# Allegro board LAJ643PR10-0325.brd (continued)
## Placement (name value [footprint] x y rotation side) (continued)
CK9  100P_0201_50V8J  [C_0201]  137.25 25.59 90 top
CK10  1000P_0402_50V8K  [C_0402]  148.19 6.57 270 top
CK11  0.1U_0402_16V7K  [C_0402]  128.42 22.22 270 top
CK12  1000P_0402_50V8K  [C_0402]  129.34 23.16 270 top
CK13  0.1U_0402_16V7K  [C_0402]  133.08 16.18 180 top
CK14  0.1U_0402_16V7K  [C_0402]  190.51 21.07 90 top
CK15  100P_0402_50V8J  [C_0402]  147.17 25.51 90 top
CK16  0.1U_0201_10V6K  [C_0201]  132.26 13.46 180 top
CL1  0.01U_0402_16V7K  [C_0402]  46.74 32.54 0 top
CL2  10P_1808_3KV  [C_1808]  41.76 43.3 270 bottom
CL3  120P_0402_50V8J  [C_0402]  34.75 43.69 270 bottom
CL4  0.1U_0402_16V7K  [C_0402]  47.66 26.44 180 top
CL5  0.1U_0201_10V6K  [C_0201]  52.15 22.97 90 bottom
CL8  4.7U_0402_6.3V6M  [C_0402]  51.51 13.39 270 bottom
CL9  0.1U_0201_10V6K  [C_0201]  59.52 20.56 90 bottom
CL10  4.7U_0402_6.3V6M  [C_0402]  54.31 15.59 270 bottom
CL11  0.1U_0201_10V6K  [C_0201]  52.15 21.45 90 bottom
CL12  0.1U_0201_10V6K  [C_0201]  59.01 23.01 0 bottom
CL13  0.1U_0201_10V6K  [C_0201]  55.16 16.03 0 bottom
CL14  0.1U_0201_10V6K  [C_0201]  55.16 14.76 0 bottom
CL15  1U_0201_6.3V6M  [C_0201]  55.16 15.39 0 bottom
CL16  0.1U_0201_10V6K  [C_0201]  54.48 16.41 180 bottom
CL19  4.7U_0402_6.3V6M  [C_0402]  51.37 23.22 180 bottom
CL20  4.7U_0402_6.3V6M  [C_0402]  60.3 20.77 90 bottom
CL23  0.1U_0201_10V6K  [C_0201]  52.27 13.23 270 bottom
CL24  10P_0402_50V8J  [C_0402]  50.88 20.34 270 bottom
CL25  10P_0402_50V8J  [C_0402]  50.88 17.68 90 bottom
CL26  0.1U_0201_10V6K  [C_0201]  55.07 23.35 90 bottom
CL27  1U_0201_6.3V6M  [C_0201]  51.05 21.49 180 bottom
CL28  1500P_0402_50V7K  [C_0402]  61.12 13.84 0 bottom
CL29  4.7U_0402_6.3V6M  [C_0402]  52.55 16.11 180 top
CLRP1  SHORT PADS  [SHORTPADS]  188.8 17.68 90 top
CLRP2  SHORT PADS  [SHORTPADS]  188.55 20.85 0 top
CLRP3  SHORT PADS  [SHORTPADS]  215.63 20.37 180 top
CR1  0.1U_0402_16V7K  [C_0402]  37.17 21.61 0 top
CR2  0.1U_0402_16V7K  [C_0402]  37.8 16.41 180 bottom
CR3  4.7U_0402_6.3V6M  [C_0402]  45.42 18.82 0 bottom
CR4  10U_0402_6.3V6M  [C_0402]  37.17 20.72 0 top
CR6  0.1U_0402_16V7K  [C_0402]  45.42 17.93 0 bottom
CR7  10U_0402_6.3V6M  [C_0402]  37.8 15.52 180 bottom
CR9  4.7U_0402_6.3V6M  [C_0402]  37.8 18.18 180 bottom
CR10  0.1U_0402_16V7K  [C_0402]  37.8 17.3 180 bottom
CR11  0.1U_0402_10V7K  [C_0402]  60.32 16.84 180 bottom
CR12  6.8P_0402_50V8C  [C_0402]  38.56 21.61 270 bottom
CR13  0.1U_0402_10V7K  [C_0402]  60.32 15.95 180 bottom
CR14  0.1U_0402_10V7K  [C_0402]  39.62 12.15 90 bottom
CR15  0.1U_0402_10V7K  [C_0402]  38.73 12.15 90 bottom
CR16  0.1U_0402_16V7K  [C_0402]  39.65 15.79 90 top
CR17  1U_0201_6.3V6M  [C_0201]  40.21 20.72 90 bottom
CS7  0.1U_0402_16V7K  [C_0402]  20.66 76.99 270 bottom
CS8  1U_0201_6.3V6M  [C_0201]  22.34 84.9 0 bottom
CS9  47U_0805_6.3V6M  [C_0805]  21.15 83.76 0 bottom
CS21  .1U_0402_16V7K  [C_0402]  20.74 82.69 90 top
CS22  10U_0603_6.3V6M  [C_0603]  21.69 76.29 270 top
CS29  0.1U_0402_16V7K  [C_0402]  21.03 90.32 0 bottom
CS34  0.1U_0402_16V7K  [C_0402]  21.03 89.43 0 bottom
CS107  0.1U_0402_16V7K  [C_0402]  23.63 76.37 270 top
CS108  0.1U_0402_25V7K  [C_0402]  18.08 82.33 180 top
CS109  1U_0201_6.3V6M  [C_0201]  20.5 85.88 180 bottom
CS110  10U_0402_6.3V6M  [C_0402]  22.74 76.37 270 top
CS111  10U_0402_6.3V6M  [C_0402]  20.46 76.37 270 top
CS113  10U_0402_6.3V6M  [C_0402]  21.63 82.69 90 top
CS114  22U_0603_6.3V6M  [C_0603]  22.69 82.8 90 top
CT3  0.1U_0201_10V6K  [C_0201]  36.15 48.16 180 top
CT5  0.1U_0201_10V6K  [C_0201]  36.45 49.55 180 top
CT17  0.1U_0201_10V6K  [C_0201]  36.15 48.79 180 top
CT19  0.1U_0201_10V6K  [C_0201]  36.45 50.19 180 top
CT20  0.1U_0201_10V6K  [C_0201]  36.33 50.95 180 top
CT21  0.1U_0201_10V6K  [C_0201]  36.33 51.59 180 top
CT22  0.1U_0201_10V6K  [C_0201]  36.33 52.35 180 top
CT24  0.1U_0201_10V6K  [C_0201]  36.33 52.98 180 top
CT270  10U_0402_6.3V6M  [C_0402]  38.5 54.46 270 top
CT271  0.1U_0201_6.3V6K  [C_0201]  27.72 54.76 180 top
CT272  0.1U_0201_6.3V6K  [C_0201]  29.21 48.4 90 bottom
CT273  0.1U_0201_6.3V6K  [C_0201]  29.86 48.4 90 bottom
CT274  0.1U_0201_6.3V6K  [C_0201]  35.53 54.19 270 top
CT279  0.22U_0201_25V6K  [C_0201]  26.73 51.78 0 top
CT280  0.22U_0201_25V6K  [C_0201]  26.73 51.14 0 top
CT281  0.22U_0201_25V6K  [C_0201]  26.73 49.92 0 top
CT282  0.22U_0201_25V6K  [C_0201]  26.73 50.56 0 top
CT283  0.1U_0201_10V6K  [C_0201]  31.72 57.29 90 top
CT284  0.1U_0201_10V6K  [C_0201]  30.83 57.29 90 top
CT285  0.1U_0201_10V6K  [C_0201]  31.91 45.73 270 top
CT286  0.1U_0201_10V6K  [C_0201]  31.32 45.73 270 top
CT287  0.1U_0201_10V6K  [C_0201]  33.89 45.88 270 top
CT288  0.1U_0201_10V6K  [C_0201]  33.29 45.88 270 top
CT319  0.33U_0201_25V6K  [C_0201]  26.27 52.99 0 top
CT320  0.33U_0201_25V6K  [C_0201]  26.27 52.36 0 top
CT321  0.33U_0201_25V6K  [C_0201]  27.06 48.11 0 top
CT322  0.33U_0201_25V6K  [C_0201]  27.06 48.74 0 top
CTT1  0.1U_0402_16V4Z  [C_0402]  119.03 13.99 180 top
CTT2  1U_0201_6.3V6M  [C_0201]  127.8 18.18 0 top
CTT3  0.1U_0402_16V4Z  [C_0402]  119.04 18.19 180 top
CTT4  0.1U_0402_16V4Z  [C_0402]  119.04 19.08 180 top
CTT323  1U_0201_6.3V6M  [C_0201]  123.99 12.98 0 top
CU57  0.47U_0402_25V6K  [C_0402]  11.62 52.71 90 top
CU58  0.47U_0402_25V6K  [C_0402]  10.73 52.71 90 top
CU59  0.47U_0402_25V6K  [C_0402]  11.19 50.95 90 top
CU60  0.47U_0402_25V6K  [C_0402]  12.08 51.84 270 top
CU61  22U_0603_6.3V6K  [C_0603]  39.92 42.83 270 top
CU62  4.7U_0402_6.3V6M  [C_0402]  41.91 41.67 90 top
CU63  1000P_0402_50V7K  [C_0402]  41.11 38.94 270 top
CU64  0.1U_0402_25V6  [C_0402]  42 38.94 270 top
CU65  1U_0603_25V6  [C_0603]  39.97 39.37 270 top
CU66  120P_0402_50V  [C_0402]  50.62 38.15 270 top
CU67  120P_0402_50V  [C_0402]  48.62 37.5 270 top
CU68  22P 50V J NPO 0402  [C_0402]  54.88 46.75 270 top
CU69  4.7U_0402_6.3V6M  [C_0402]  52.75 43.56 0 top
CU70  10U_0402_6.3V6M  [C_0402]  42 46.11 180 top
CU71  10U_0402_6.3V6M  [C_0402]  39.37 47.78 0 top
CU72  0.1U_0402_16V4Z  [C_0402]  60.92 23.31 0 bottom
CU73  4.7U_0402_6.3V6M  [C_0402]  49.7 38.15 270 top
CU74  4.7U_0402_6.3V6M  [C_0402]  55.4 44.5 270 top
CV1  22U_0603_6.3V6M  [C_0603]  73.8 37.11 0 top
CV2  68P_0402_50V8J  [C_0402]  78.01 38.76 180 top
CV3  22U_0603_6.3V6M  [C_0603]  68.48 33.89 180 top
CV4  22U_0603_6.3V6M  [C_0603]  69.66 32.74 0 top
CV5  680P_0402_50V7K  [C_0402]  79.41 30.76 180 top
CV6  68P_0402_50V8J  [C_0402]  79.41 29.87 180 top
CV7  .1U_0402_16V7K  [C_0402]  73.5 27.25 90 bottom
CV8  .1U_0402_16V7K  [C_0402]  72.61 27.25 90 bottom
CV9  .1U_0402_16V7K  [C_0402]  75.32 27.25 90 bottom
CV10  .1U_0402_16V7K  [C_0402]  74.43 27.25 90 bottom
CV11  .1U_0402_16V7K  [C_0402]  77.13 27.25 90 bottom
CV12  .1U_0402_16V7K  [C_0402]  76.24 27.25 90 bottom
CV13  .1U_0402_16V7K  [C_0402]  78.95 27.25 90 bottom
CV14  .1U_0402_16V7K  [C_0402]  78.06 27.25 90 bottom
CV15  .1U_0402_16V7K  [C_0402]  80.85 27.25 90 bottom
CV16  .1U_0402_16V7K  [C_0402]  79.96 27.25 90 bottom
CV17  220P_0402_50V7K  [C_0402]  71.63 24.32 270 bottom
CV18  220P_0402_50V7K  [C_0402]  71.79 26.27 270 bottom
CV19  4.7U_0402_6.3V6M  [C_0402]  28.77 59.03 0 top
CV20  0.1U_0402_10V6K  [C_0402]  25.84 58.82 90 top
CV21  0.1U_0402_10V6K  [C_0402]  27.21 58.84 90 top
CV22  0.01U_0402_16V7K  [C_0402]  24.49 58.8 90 top
CV23  0.1U_0402_10V6K  [C_0402]  23.22 58.24 90 top
CV24  0.1U_0402_10V6K  [C_0402]  22.73 62.62 0 top
CV25  0.01U_0402_16V7K  [C_0402]  25.87 64.01 270 top
CV26  0.1U_0402_10V6K  [C_0402]  28.99 59.96 180 top
CV27  0.1U_0402_10V6K  [C_0402]  22.76 61.28 0 top
CV28  0.01U_0402_16V7K  [C_0402]  24.51 63.99 270 top
CV29  0.1U_0402_10V6K  [C_0402]  27.21 64 270 top
CV30  0.01U_0402_16V7K  [C_0402]  28.76 61.28 180 top
CV31  0.1U_0402_10V6K  [C_0402]  28.07 66.19 90 top
CV32  0.01U_0402_16V7K  [C_0402]  28.15 66.29 90 bottom
CV33  0.1U_0402_10V6K  [C_0402]  20.66 57.33 270 top
CV34  0.1U_0402_10V6K  [C_0402]  31.33 57.34 180 bottom
CV35  0.1U_0402_10V6K  [C_0402]  31.33 56.38 180 bottom
CV36  0.1U_0402_10V6K  [C_0402]  26.88 55.5 90 bottom
CV37  0.1U_0402_10V6K  [C_0402]  25.99 55.5 90 bottom
CV38  0.1U_0402_10V6K  [C_0402]  24.97 55.5 90 bottom
CV39  0.1U_0402_10V6K  [C_0402]  24.08 55.5 90 bottom
CV40  0.1U_0402_10V6K  [C_0402]  23.07 55.5 90 bottom
CV41  0.1U_0402_10V6K  [C_0402]  22.18 55.5 90 bottom
CV43  1U_0201_6.3V6M  [C_0201]  28.28 56.24 90 top
CV44  1U_0201_6.3V6M  [C_0201]  21.39 56.28 90 top
CV45  .1U_0402_16V7K  [C_0402]  15.08 117.23 90 top
CV46  10P_0402_50V8J  [C_0402]  68.15 32.66 180 top
CV47  33P_0402_50V8J  [C_0402]  69.84 31.69 0 top
CV49  680P_0402_50V7K  [C_0402]  69.6 39.52 0 top
CV52  1000P_0402_50V7K  [C_0402]  15.97 118.12 270 top
CV53  1U_0201_6.3V6M  [C_0201]  27.65 56.24 90 top
CV54  10U_0402_6.3V6M  [C_0402]  87.54 33.46 0 top
CV273  2200P_0402_50V7K  [C_0402]  180.37 121.44 180 bottom
CV274  0.1U_0402_16V4K  [C_0402]  181.31 121.51 270 bottom
CV275  3.3P_0201_25V8B  [C_0201]  20.68 109.92 90 bottom
CW1  10U_0402_6.3V6M  [C_0402]  304.91 7.05 270 top
CWL1  100P_0402_50V8J  [C_0402]  310.09 21.82 0 top
CWL2  10U_0402_6.3V6M  [C_0402]  310.1 23.59 0 top
CWL3  10U_0402_6.3V6M  [C_0402]  307.4 7.96 180 top
CWL4  0.1U_0402_10V6K  [C_0402]  310.08 24.48 0 top
CWL5  0.1U_0402_10V6K  [C_0402]  307.4 7.01 180 top
CWL7  0.01U_0402_16V7K  [C_0402]  310.09 22.71 0 top
CWL8  0.01U_0402_16V7K  [C_0402]  310.65 6.5 0 top
D1  AZ5123-02S.R7G_SOT23-3  [AZ5123-02SPR7G_SOT23-3]  10.42 122.73 90 top
D3  AZ5123-02S.R7G_SOT23-3  [AZ5123-02SPR7G_SOT23-3]  207.98 128.93 0 top
D506  -  [AZC199-02SPR7G_SOT23-3]  65.31 28.08 0 bottom
D507  -  [AZC199-02SPR7G_SOT23-3]  69.27 25.07 180 bottom
D508  LRB751V-40T1G SOD-323  [CH751H-40PT_SOD323-2]  205.95 135.28 270 top
D510  RB751V-40 SOD-323  [CH751H-40PT_SOD323-2]  128.44 9.29 0 top
D511  LRB751V-40T1G_SOD323-2  [CH751H-40PT_SOD323-2]  182.38 48.74 270 top
D513  LRB751V-40T1G_SOD323-2  [CH751H-40PT_SOD323-2]  38.82 2.56 90 bottom
D514  RB751V-40 SOD-323  [CH751H-40PT_SOD323-2]  128.44 7.64 0 top
D516  LRB751V-40T1G_SOD323-2  [CH751H-40PT_SOD323-2]  176.03 45.97 90 top
D517  RB751V-40 SOD-323  [CH751H-40PT_SOD323-2]  111.71 25.17 270 top
DA1  AZ5125-01H.R7G_SOD523-2  [AZ5125-01HPR7G_SOD523-2]  289.01 25.93 180 top
DA3  -  [LRB521S-40T1G_SOD523-2-2]  292.82 12.85 90 top
DA8  -  [L03ESDL5V0CC3-2_SOT23-3]  295.76 37.86 270 top
DA9  -  [L03ESDL5V0CC3-2_SOT23-3]  295.76 41.96 270 top
DG1  -  [RB751S40T1G_SOD523-2]  245.95 39.77 0 bottom
DG2  -  [RB751S40T1G_SOD523-2]  220.49 64.84 90 top
DG3  -  [BAV70W_SOT323-3]  236.53 50.72 45 top
DG4  -  [RB751S40T1G_SOD523-2]  235.29 41.68 0 bottom
DG5  -  [RB751S40T1G_SOD523-2]  238.21 41.55 90 bottom
DG7  -  [RB751S40T1G_SOD523-2]  235.28 42.87 0 bottom
DG243  -  [RB751S40T1G_SOD523-2]  224.15 63.95 90 top
DH1  LBAT54CLT1G_SOT23-3  [BAT54C-7-F_SOT23-3]  179.99 12.52 90 top
DH2  LRB751V-40T1G_SOD323-2  [CH751H-40PT_SOD323-2]  191.22 16.28 0 top
DH3  LRB751V-40T1G_SOD323-2  [CH751H-40PT_SOD323-2]  188.68 14.63 0 top
DH4  LRB751V-40T1G_SOD323-2  [CH751H-40PT_SOD323-2]  204.67 6.32 0 top
DK2  LRB751V-40T1G_SOD323-2  [CH751H-40PT_SOD323-2]  131.57 20.97 90 top
DL1  -  [AZC199-02SPR7G_SOT23-3]  38.13 39.04 180 bottom
DM5  AZC099-04S.R7G_SOT23-6  [AZC099-04SPR7G_SOT23-6]  85.51 11.44 270 top
DM12  AZC099-04S.R7G_SOT-23-6-6  [YSUSB2P0-5_SOT-23-6-6]  52.56 27.76 270 bottom
DM13  AZC099-04S.R7G_SOT-23-6-6  [YSUSB2P0-5_SOT-23-6-6]  52.56 34.11 270 bottom
DM16  -  [AZC199-02SPR7G_SOT23-3]  8.13 59.97 270 top
DS5  -  [AZC199-02SPR7G_SOT23-3]  20.52 88.8 90 top
DS6  -  [AZ1045-04F_DFN2510P10E-10-9]  17.73 88.03 90 bottom
DT1  -  [AZC199-02SPR7G_SOT23-3]  95.2 14.53 180 top
DT2  LRB751V-40T1G_SOD323-2  [CH751H-40PT_SOD323-2]  20.87 51.97 180 bottom
DU1  -  [PUSB3FR4_DFN2510A-10-10]  14.08 53.16 270 top
DU2  -  [PUSB3FR4_DFN2510A-10-10]  14.08 51.13 90 bottom
DU3  AZ1045-04F  [PUSB3FR4_DFN2510A-10-10]  15.77 47.44 90 top
DU13  -  [L30ESD24VC3-2_SOT23-3]  11.13 44.85 0 top
DU14  -  [AZC199-02SPR7G_SOT23-3]  15.96 48.28 90 bottom
DV1  -  [AZ1045-04F_DFN2510P10E-10-9]  16.09 116.09 270 bottom
DV2  -  [AZ1045-04F_DFN2510P10E-10-9]  16.09 112.02 270 bottom
DV3  -  [AZ1045-04F_DFN2510P10E-10-9]  16.09 108.72 270 bottom
EC11  VARIST_ CK0402101V05 0402  [CK0402101V05_0402-2]  18.37 7.42 270 top
FD1  -  [FIDUCIAL_C40M80]  20.15 103.91 0 top
FD2  -  [FIDUCIAL_C40M80]  290.28 7.14 0 top
FD3  -  [FIDUCIAL_C40M80]  234.29 121.59 180 bottom
FD4  -  [FIDUCIAL_C40M80]  3 3.58 180 bottom
FU1  0.5A_15V_MF-MSMF050-2~D  [F_MF-MSMF050-2]  86.36 29.36 180 top
H1  -  [H_2P3-G]  179 133.9 0 top
H2  -  [H_2P3-G]  229.5 7.9 0 top
H4  -  [H_2P3-G]  93 52.9 0 top
H7  -  [H_2P3-G]  49.05 5.9 0 top
H8  -  [H_2P3-G]  267.5 52.9 0 top
H9  -  [H_2P3-G]  295.7 7.9 0 top
H11  -  [H_2P3-G]  15.94 58.89 0 top
H12  -  [H_4P1]  121.6 119.23 0 top
H13  -  [H_4P1]  175.6 116.08 0 top
H14  -  [H_4P1]  231.87 111.99 0 top
H15  -  [H_4P1]  117.18 79.83 0 top
H16  -  [H_2P3-G]  3.5 125.9 0 top
H17  -  [H_2P3-G]  12 4 0 top
H18  -  [H_4P1]  176.02 75.43 0 top
H19  -  [H_4P1]  180.53 63.65 0 top
H20  -  [H_4P1]  247.76 50.69 0 top
H22  -  [H_2P3X2P8]  3 9 90 top
H23  -  [H_2P3-G]  24 115.28 0 top
H25  -  [H_2P3N]  201.3 135.87 0 top
H33  -  [H_4P0-G]  256 68.9 0 top
H34  -  [H_2P4-G]  26.5 108.65 0 top
JCR2  T-SOL_5-531809001000-6  [T-SOL_5-531809001000-6_15P-T]  34 19.7 90 bottom
JDIMM1  ARGOS_D4AR0-26015-1P40  [ARGOS_D4AR0-26015-1P40_260P]  104.02 50.25 0 bottom
JDIMM2  ARGOS_D4AS0-26010-1P40  [ARGOS_D4AS0-26010-1P40_260P]  102.53 38 180 bottom
JEDP1  ACES_51519-04001-001  [ACES_51519-04001-001_40P-T]  61.05 30.4 0 bottom
JFAN1  ACES_50224-00401-001  [ACES_50224-00401-001_4P]  274.99 47.38 180 bottom
JFAN2  ACES_50224-00401-001  [ACES_50224-00401-001_4P]  41.82 45.9 90 bottom
JHDD1  CVILU_CF3112DD0R4-05-NH  [CVILU_CF3112DD0R4-05-NH_12P]  251.15 15.95 180 bottom
JHDMI1  -  [ACON_HMRA3-AK120C_19P]  10.75 107.15 90 bottom
JIO1  JXT_FP243A-036G1BM  [JXT_FP243A-036G1BM_36P]  308.68 45.75 270 bottom
JKB1  SDAN_606011-032241  [SDAN_606011-032241_32P]  175.35 12.5 180 bottom
JKBL1  ACES_51575-00401-001  [ACES_51575-00401-001_4P]  216.9 11.42 180 bottom
JL33  -  [JUMP_43X79]  55.3 15.61 180 top
JP3  -  [JUMP_43X79]  181.44 31.77 270 top
JP4  -  [JUMP_43X79]  38.69 13.61 270 top
JPHW8  -  [JUMP_43X118]  38 39.75 180 top
JPWR1  JXT_FP241AH-006GAAM  [JXT_FP241AH-006GAAM_6P]  9.75 123.26 0 bottom
JRJ45  SDAN_601051-008041  [SDAN_601051-008041_8P]  12.84 74.79 90 bottom
JSPK1  ACES_50271-0060N-001  [ACES_50271-0060N-001_6P-T]  303.73 46.09 180 bottom
JSSD1  ARGOS_NFSM0-S6715-TPH4  [ARGOS_NFSM0-S6715-TPH4_67P]  35.85 9.33 180 bottom
JTP1  TWVM_FPC1020-08RC-MA0HA  [TWVM_FPC1020-08RC-MA0HA_8P]  92.2 13.5 180 bottom
JUSB3  ACON_TCRAR-9U1391  [ACON_TCRAR-9U1391_9P-T]  14.7 92.35 90 bottom
JUSBC1  SUYIN_020090HB024M51HZL  [SUYIN_020090HB024M51HZL_24P-T-S]  7.5 55.19 270 top
JWLAN1  LOTES_APCI0019-P003H  [LOTES_APCI0019-P003H_67P]  302.82 24.6 270 bottom
L1  DLM0NSN900HY2D_4P  [MURAT_DLM0NSN900HY2D_4P]  68.72 22.77 90 bottom
LA1  SUPPRE_ KC FBMA-10-100505-101T 0402  [R_0402]  289.51 10.69 180 top
LA2  0_0603_5%  [R0603_0OHM]  290.4 24.79 90 top
LA3  0_0402_5%  [R0402_0OHM]  301.33 21.99 0 top
LA4  FBMA-L11-201209601LMA20T_2P  [C_0805]  288.88 16.66 180 top
LA8  BLM15AX601SN1D_2P  [MURAT_BLM15AX601SN1D_2P]  304.12 28.22 180 bottom
LA9  BLM15AX601SN1D_2P  [MURAT_BLM15AX601SN1D_2P]  304.12 29.49 180 bottom
LA10  BLM15AX601SN1D_2P  [MURAT_BLM15AX601SN1D_2P]  304.12 30.63 180 bottom
LED4  LTST-S270KFKT-5A  [LED_LTST-S270KFKT-5A_2P]  2.5 62.4 270 bottom
LED5  LTW-482DS5  [LED_LTW-482DS5_2P]  2.77 60.58 90 top
LG1  CHILISIN PBY160808T-330Y-N  [MURAT_BLM18PG330SN1D_2P]  193.93 80.41 90 top
LG3  CHILISIN PBY160808T-330Y-N  [MURAT_BLM18PG330SN1D_2P]  188.8 95.91 270 bottom
LK1  S SUPPRE_ TAI-TECH HCB1005KF-221T15 0402  [MURAT_BLM15BD601SN1D_2P]  151.73 26.47 270 top
LK2  TAI-TECH HCB1005KF-221T15 0402  [MURAT_BLM15BD601SN1D_2P]  149.36 26.49 270 top
LL2  2.2UH_MHCD252012A-2R2M-A8S_2A_20%  [CHILI_MHCD252012A-2R2M-A8S_2P]  52.28 16.39 270 bottom
LM13  HCM1012GH900BP_4P  [INPAQ_HCM1012GH900BP_4P]  19.59 110.47 180 bottom
LS9  DLM0NSN900HY2D_4P  [MURAT_DLM0NSN900HY2D_4P]  19.96 85.82 90 top
LV1  0_0805_5%  [R_0805]  87.84 36.18 270 top
LV2  3A_Z120_40M_0603_2P  [CHILI_PBY160808T-121Y-N_2P]  73.86 35.77 0 top
LV3  2.2UH_MHCD252012A-2R2M-A8S_2A_20%  [CHILI_MHCD252012A-2R2M-A8S_2P]  70.31 37.47 270 top
ML11  DLM0NSN900HY2D_4P  [MURAT_DLM0NSN900HY2D_4P]  17.85 48.96 180 top
NOREF  -  []  117.18 79.83 0 top
NOREF#2  -  []  125.63 70.69 0 top
NOREF#3  -  []  223.55 36.83 0 top
NOREF#4  -  []  177.5 158.9 0 top
NOREF#5  -  []  247.76 50.69 0 top
NOREF#6  -  []  229.5 7.9 0 top
NOREF#7  -  []  180.53 63.65 0 top
NOREF#8  -  []  112.88 62.81 0 top
NOREF#9  -  []  140.94 -13.55 0 top
NOREF#10  -  []  12 4 0 top
NOREF#11  -  []  93 52.9 0 top
NOREF#12  -  []  206.08 47.65 0 top
NOREF#13  -  []  64.85 -30.38 0 top
NOREF#14  -  []  267.5 52.9 0 top
NOREF#15  -  []  256 68.9 0 top
NOREF#16  -  []  175.6 116.08 0 top
NOREF#17  -  []  121.6 119.23 0 top
NOREF#18  -  []  176.02 75.43 0 top
NOREF#19  -  []  179 133.9 0 top
NOREF#20  -  []  231.87 111.99 0 top
NOREF#21  -  []  295.7 7.9 0 top
NOREF#22  -  []  272.88 30.99 180 bottom
NOREF#23  -  []  156.8 66.57 180 bottom
NOREF#24  -  []  228.16 34.95 180 bottom
NOREF#25  -  []  227.78 28.66 270 bottom
PC1  0.022U_0402_25V7K  [C_0402]  279.79 29.64 270 top
PC2  2200P_0402_50V7K  [C_0402]  280.73 29.64 270 top
PC3  2200P_0402_50V7K  [C_0402]  276.27 36.01 90 top
PC4  1000P_0402_50V7K  [C_0402]  275.38 36.01 90 top
PC5  100P_0402_50V8J  [C_0402]  285.32 40.08 90 top
PC6  1000P_0402_50V7K  [C_0402]  284.43 40.08 90 top
PC8  1000P_0402_50V7K  [C_0402]  274.24 10.23 90 bottom
PC9  0.01U_0402_25V7K  [C_0402]  272.42 10.24 90 bottom
PC10  100P_0402_50V8J  [C_0402]  273.32 10.23 90 bottom
PC11  100P_0402_50V8J  [C_0402]  271.51 10.23 90 bottom
PC301  0.1U_0402_25V6  [C_0402]  246.59 28.86 180 bottom
PC302  0.1U_0402_25V6  [C_0402]  244.91 27.96 180 bottom
PC303  2200P_0402_50V7K  [C_0402]  247.47 34.53 0 bottom
PC305  10U_0603_25V6M  [C_0603-H1_2]  247.59 33.45 0 bottom
PC306  22U_0603_6.3V6M  [C_0603]  240.81 17.72 180 bottom
PC307  22U_0603_6.3V6M  [C_0603]  240.83 20.16 180 bottom
PC308  22U_0603_6.3V6M  [C_0603]  250.11 19.53 0 bottom
PC309  22U_0603_6.3V6M  [C_0603]  240.83 18.93 180 bottom
PC310  4.7U_0402_6.3V6M  [C_0402]  252.39 27.54 270 bottom
PC311  680P_0402_50V7K  [C_0402]  250.12 20.62 0 bottom
PC312  1000P_0402_50V7K  [C_0402]  252.72 29.83 0 bottom
PC313  0.1U_0402_25V6  [C_0402]  75.75 6.68 180 top
PC314  10U_0603_25V6M  [C_0603-H1_2]  79.23 5.78 90 bottom
PC316  2200P_0402_50V7K  [C_0402]  80.29 5.76 90 bottom
PC317  0.1U_0402_25V6  [C_0402]  81.22 5.76 90 bottom
PC318  2.2U_0402_6.3V6M  [C_0402]  78.96 9.58 0 bottom
PC319  22U_0603_6.3V6M  [C_0603]  63.45 9.61 180 bottom
PC320  22U_0603_6.3V6M  [C_0603]  63.46 8.32 180 bottom
PC321  22U_0603_6.3V6M  [C_0603]  63.41 10.93 180 top
PC322  22U_0603_6.3V6M  [C_0603]  64.48 5.78 180 top
PC323  22U_0603_6.3V6M  [C_0603]  63.46 8.32 180 top
PC324  22U_0603_6.3V6M  [C_0603]  63.41 7 180 top
PC325  680P_0402_50V7K  [C_0402]  69.98 8.13 0 top
PC326  4.7U_0402_6.3V6M  [C_0402]  78.96 10.55 0 bottom
PC327  1000P_0402_50V7K  [C_0402]  76.96 11.81 90 bottom
PC328  4.7U_0402_6.3V6M  [C_0402]  252.52 30.69 90 bottom
PC329  1U_0402_25V6K  [C_0402]  75.01 11.72 0 bottom
PC330  22U_0603_6.3V6M  [C_0603]  63.42 10.94 180 bottom
PC331  22U_0603_6.3V6M  [C_0603]  64.49 5.76 180 bottom
PC332  22U_0603_6.3V6M  [C_0603]  63.45 9.61 180 top
PC333  22U_0603_6.3V6M  [C_0603]  63.42 6.99 180 bottom
PC1001  0.1U_0402_25V6  [C_0402]  240.73 25.69 0 bottom
PC1002  0.1U_0402_25V6  [C_0402]  234.73 30.15 270 bottom
PC1003  680P_0603_50V8J  [C_0603]  234.57 25.74 270 top
PC1004  22U_0603_6.3V6M  [C_0603]  234.58 19.92 0 bottom
PC1005  22U_0603_6.3V6M  [C_0603]  234.57 18.68 0 bottom
PC1006  22U_0603_6.3V6M  [C_0603]  234.59 21.12 0 bottom
PC1007  22U_0603_6.3V6M  [C_0603]  234.62 22.34 0 bottom
PC1008  330P_0402_50V7K  [C_0402]  237.83 22.08 0 bottom
PC1010  2.2U_0402_6.3V6M  [C_0402]  235.92 24.27 270 bottom
PC1011  2200P_0402_50V7K  [C_0402]  241.28 29.01 270 bottom
PC1012  0.1U_0402_25V6  [C_0402]  237.43 30.01 90 bottom
PC1013  10U_0603_25V6M  [C_0603-H1_2]  242.35 29.57 270 bottom
PC1014  1U_0402_16V6K  [C_0402]  236.82 24.28 270 bottom
PC1801  22U_0603_6.3V6M  [C_0603]  267.19 19.71 270 bottom
PC1802  22P_0402_50V8J  [C_0402]  265.21 22.47 0 bottom
PC1803  22U_0603_6.3V6M  [C_0603]  259.44 21.54 0 bottom
PC1804  22U_0603_6.3V6M  [C_0603]  259.63 17.57 0 bottom
PC1805  0.1U_0402_16V7K  [C_0402]  262.68 23.39 180 bottom
PC1806  680P_0402_50V7K  [C_0402]  265.14 18.52 0 bottom
PC2501  22U_0603_6.3V6M  [C_0603]  103.67 17.57 0 top
PC2502  0.47U_0402_6.3V6K  [C_0402]  109.49 14.49 270 top
PC2503  680P_0402_50V7K  [C_0402]  109.54 19.91 270 top
PC2504  68P_0402_50V8J  [C_0402]  104.23 14.92 0 top
PC2505  22U_0603_6.3V6M  [C_0603]  110.99 16 270 top
PC2506  22U_0603_6.3V6M  [C_0603]  112.24 16 270 top
PCA1  10U_0603_25V6M  [C_0603-H1_2]  157.88 127.79 0 top
PCA2  10U_0603_25V6M  [C_0603-H1_2]  157.88 127.79 0 bottom
PCA3  0.1U_0402_25V6  [C_0402]  158.12 125.75 0 top
PCA4  2200P_0402_50V7K  [C_0402]  158.12 126.64 0 top
PCA5  0.22U_0603_25V7K  [C_0603]  158.07 131.79 270 bottom
PCA6  2.2U_0402_6.3V6M  [C_0402]  160.86 134.82 90 bottom
PCA7  680P_0402_50V7K  [C_0402]  159.97 124.31 270 top
PCA23  1U_0201_6.3V6M  [C_0201]  160.69 101.23 0 top
PCA25  22U_0603_6.3V6M  [C_0603]  159.78 100.35 180 top
PCA26  22U_0603_6.3V6M  [C_0603]  159.78 96.54 180 top
PCA27  22U_0603_6.3V6M  [C_0603]  160.99 95.08 270 top
PCA28  22U_0603_6.3V6M  [C_0603]  160.99 99.91 270 top
PCA29  22U_0603_6.3V6M  [C_0603]  159.78 99.08 180 top
PCA30  22U_0603_6.3V6M  [C_0603]  159.78 95.27 180 top
PCA31  22U_0603_6.3V6M  [C_0603]  160.99 96.1 90 top
PCA32  22U_0603_6.3V6M  [C_0603]  159.78 101.62 180 top
PCA33  22U_0603_6.3V6M  [C_0603]  159.78 97.81 180 top
PCA34  22U_0603_6.3V6M  [C_0603]  159.78 93.88 180 top
PCB01  2200P_0402_50V7K  [C_0402]  267.96 29.45 180 top
PCB02  0.22U_0402_25V6K  [C_0402]  266.3 36.29 180 top
PCB03  0.033U_0402_25V7K  [C_0402]  233.67 14.85 0 top
PCB04  0.1U_0402_25V6  [C_0402]  235.48 13.86 90 top
PCB05  0.1U_0402_25V6  [C_0402]  235.48 15.6 90 top
PCB08  1200P_0402_50V7K  [C_0402]  247.71 10.22 270 top
PCB09  1200P_0402_50V7K  [C_0402]  246.81 10.23 270 top
PCB10  10U_0603_25V6M  [C_0603-H1_2]  250.04 10.36 270 top
PCB11  10U_0603_25V6M  [C_0603-H1_2]  248.8 10.36 270 top
PCB12  0.1U_0402_25V6  [C_0402]  265.07 12.58 180 bottom
PCB14  2.2U_0402_25V6M  [C_0402]  240.86 9.81 180 bottom
PCB15  0.22U_0603_25V7K  [C_0603]  238.14 14.76 0 top
PCB16  0.1U_0402_25V6  [C_0402]  236.24 10.55 0 bottom
PCB17  0.47U_0402_25V6K  [C_0402]  243.48 11.53 180 top
PCB18  680P_0603_50V8J  [C_0603]  253.47 6.26 180 top
PCB19  10U_0603_25V6M  [C_0603]  270.17 10.34 90 bottom
PCB20  10U_0603_25V6M  [C_0603]  272.01 10.37 90 top
PCB22  0.1U_0402_25V6  [C_0402]  240.32 6.48 180 top
PCB23  0.1U_0402_25V6  [C_0402]  238.53 6.55 270 top
PCB24  0.1U_0402_25V6  [C_0402]  242.01 6.64 270 top
PCB26  560P_0402_50V7K  [C_0402]  234.55 6.73 180 top
PCB27  0.033U_0402_25V7K  [C_0402]  234.55 5.84 180 top
PCB29  1U_0402_16V6K  [C_0402]  243.2 9.73 90 top
PCB30  1U_0402_16V6K  [C_0402]  244.03 8.24 0 top
PCB31  2200P_0402_50V7K  [C_0402]  156.21 25.44 0 top
PCB32  2200P_0402_50V7K  [C_0402]  154.56 25.6 90 top
PCB33  10U_0603_25V6M  [C_0603]  273.65 10.37 90 top
PCB34  10U_0603_25V6M  [C_0603]  270.21 10.32 90 top
PCB35  1U_0402_16V6K  [C_0402]  248.07 7.05 0 top
PCB36  2.2U_0402_25V6M  [C_0402]  240.86 10.78 180 bottom
PCF1  22U_0603_6.3V6M  [C_0603]  174.56 99.32 135 bottom
PCF2  68P_0402_50V8J  [C_0402]  177.81 104.26 225 bottom
PCF3  22U_0603_6.3V6M  [C_0603]  180.35 98.03 135 bottom
PCF4  22U_0603_6.3V6M  [C_0603]  181.25 98.93 135 bottom
PCF5  .1U_0402_16V7K  [C_0402]  178.87 101.83 45 bottom
PCF6  680P_0402_50V7K  [C_0402]  174.85 98.05 45 bottom
PCG1  2200P_0402_50V7K  [C_0402]  111.94 92.35 90 top
PCG2  0.1U_0402_25V6  [C_0402]  110.62 92.34 90 top
PCG3  10U_0603_25V6M  [C_0603-H1_2]  108.54 90.96 90 bottom
PCG4  10U_0603_25V6M  [C_0603-H1_2]  115.27 92.99 90 bottom
PCG5  0.22U_0402_25V6K  [C_0402]  115.73 93.29 90 top
PCG6  2.2U_0402_6.3V6M  [C_0402]  119.79 96.37 180 top
PCG7  680P_0402_50V7K  [C_0402]  110.65 95.1 270 top
PCG55  330U_D1_2VY_R9M  [C_D2]  120.6 97.2 270 bottom
PCG56  220U_D1_2VY_R9M  [C_D2]  115.78 107.72 45 bottom
PCG57  22U_0603_6.3V6M  [C_0603]  135.83 101.57 0 top
PCG58  22U_0603_6.3V6M  [C_0603]  132.99 103.4 0 top
PCG59  22U_0603_6.3V6M  [C_0603]  132.42 92.72 90 top
PCG60  22U_0603_6.3V6M  [C_0603]  132.39 101.23 270 top
PCG61  22U_0603_6.3V6M  [C_0603]  132.42 96.48 270 top
PCG62  22U_0603_6.3V6M  [C_0603]  134.05 92.1 0 top
PCG63  22U_0603_6.3V6M  [C_0603]  139.64 101.57 180 top
PCG64  22U_0603_6.3V6M  [C_0603]  132.36 97.47 90 top
PCG65  22U_0603_6.3V6M  [C_0603]  140.63 101.57 0 top
PCG66  22U_0603_6.3V6M  [C_0603]  138.52 92.15 0 top
PCG75  1U_0201_6.3V6M  [C_0201]  140.86 103.12 0 top
PCG76  1U_0201_6.3V6M  [C_0201]  139.64 103.71 180 top
PCG77  1U_0201_6.3V6M  [C_0201]  135.76 103.69 180 top
PCG78  1U_0201_6.3V6M  [C_0201]  138.22 103.69 180 top
PCG79  1U_0201_6.3V6M  [C_0201]  136.42 103.13 0 top
PCG80  1U_0201_6.3V6M  [C_0201]  137.71 91.87 180 top
PCG81  1U_0201_6.3V6M  [C_0201]  140.86 103.68 0 top
PCG82  1U_0201_6.3V6M  [C_0201]  139.64 103.12 180 top
PCG83  1U_0201_6.3V6M  [C_0201]  135.76 103.12 180 top
PCG84  1U_0201_6.3V6M  [C_0201]  138.22 103.13 180 top
PCG85  1U_0201_6.3V6M  [C_0201]  136.42 103.69 0 top
PCG86  1U_0201_6.3V6M  [C_0201]  137.71 92.45 180 top
PCH1  2200P_0402_50V7K  [C_0402]  187.53 102 0 bottom
PCH2  680P_0402_50V7K  [C_0402]  181.06 111.66 45 top
PCH3  0.1U_0402_25V6  [C_0402]  187.53 103.02 0 bottom
PCH4  0.1U_0402_25V6  [C_0402]  188.36 104.94 180 bottom
PCH5  10U_0603_25V6M  [C_0603-H1_2]  186.28 99.82 180 bottom
PCH6  330P_0402_50V7K  [C_0402]  180.25 105.29 270 bottom
PCH7  22U_0603_6.3V6M  [C_0603]  179.41 113.82 45 bottom
PCH8  22U_0603_6.3V6M  [C_0603]  179.15 108.99 315 bottom
PCH9  22U_0603_6.3V6M  [C_0603]  177.63 110.77 135 bottom
PCH10  22U_0603_6.3V6M  [C_0603]  178.26 108.1 315 bottom
PCH11  22U_0603_6.3V6M  [C_0603]  176.74 109.88 135 bottom
PCH12  2.2U_0402_6.3V6M  [C_0402]  182.59 105.84 0 bottom
PCH13  0.1U_0402_25V6  [C_0402]  182.55 100 0 bottom
PCH14  1U_0402_16V6K  [C_0402]  181.48 106.16 180 bottom
PCM1  2200P_0402_50V7K  [C_0402]  91.61 39.08 180 top
PCM2  10U_0603_25V6M  [C_0603-H1_2]  92.18 38 180 top
PCM4  0.1U_0402_25V6  [C_0402]  89.82 30.99 270 bottom
PCM5  10U_0402_6.3V6M  [C_0402]  93.61 30.23 90 bottom
PCM6  10U_0402_6.3V6M  [C_0402]  95.06 27.72 0 bottom
PCM7  1U_0402_16V6K  [C_0402]  88.47 27.72 270 bottom
PCM8  22U_0603_6.3V6M  [C_0603]  88.33 41.42 180 bottom
PCM9  22U_0603_6.3V6M  [C_0603]  95.66 41.52 0 bottom
PCM10  22U_0603_6.3V6M  [C_0603]  95.66 41.52 0 top
PCM11  22U_0603_6.3V6M  [C_0603]  95.66 42.79 0 top
PCM12  22U_0603_6.3V6M  [C_0603]  88.33 40.15 180 bottom
PCM13  22U_0603_6.3V6M  [C_0603]  95.66 42.79 0 bottom
PCM14  680P_0402_50V7K  [C_0402]  94.68 30.69 90 top
PCM15  0.033U_0402_16V7K  [C_0402]  94.87 26.57 0 bottom
PCM16  1U_0402_16V6K  [C_0402]  88.49 25.97 270 bottom
PCM17  0.1U_0402_10V7K  [C_0402]  91.68 23.42 0 bottom
PCM18  0.1U_0402_10V7K  [C_0402]  93.54 23.5 270 bottom
PCP1  0.01U_0402_50V7K  [C_0402]  81.18 43.2 180 top
PCP2  10U_0603_25V6M  [C_0603-H1_2]  81.17 42.06 180 top
PCP3  1U_0201_6.3V6M  [C_0201]  80.42 36.05 270 top
PCP4  0.1U_0402_10V7K  [C_0402]  80.65 33.68 0 top
PCP5  10U_0603_25V6M  [C_0603-H1_2]  86.81 30.33 0 bottom
PCP6  10U_0603_25V6M  [C_0603-H1_2]  86.61 32.15 0 top
PCP7  680P_0402_50V7K  [C_0402]  86.12 34.99 180 top
PCP8  1000P_0402_50V7K  [C_0402]  85.03 32.12 90 top
PCP326  10U_0603_25V6M  [C_0603-H1_2]  86.65 32.15 0 bottom
PCP327  1U_0201_6.3V6M  [C_0201]  77.48 34.26 0 top
PCP328  1U_0201_6.3V6M  [C_0201]  77.49 34.85 0 top
PCP329  1U_0201_6.3V6M  [C_0201]  77.49 35.46 0 top
PCP330  1U_0201_6.3V6M  [C_0201]  79.24 36.05 270 top
PCP331  1U_0201_6.3V6M  [C_0201]  79.85 36.05 270 top
PCV1  0.1U_0402_25V6  [C_0402]  225.18 51.7 90 bottom
PCV2  0.1U_0402_25V6  [C_0402]  217.2 55.83 90 top
PCV3  2200P_0402_50V7K  [C_0402]  216.25 55.85 90 top
PCV4  10U_0603_25V6M  [C_0603-H1_2]  217.34 55.6 90 bottom
PCV5  10U_0603_25V6M  [C_0603-H1_2]  216.11 55.58 90 bottom
PCV6  100U_25V_NC_6.3X6  [C_6P3X6]  230.9 50.21 270 bottom
PCV7  100U_25V_NC_6.3X6  [C_6P3X6]  223.4 50.22 270 bottom
PCV8  680P_0402_50V7K  [C_0402]  204.83 58.82 270 top
PCV9  0.1U_0402_25V6  [C_0402]  225.15 57.91 270 top
PCV10  0.1U_0402_25V6  [C_0402]  230.6 52.68 180 bottom
PCV11  0.1U_0402_25V6  [C_0402]  209.27 55.99 90 top
PCV12  2200P_0402_50V7K  [C_0402]  208.37 55.99 90 top
PCV13  10U_0603_25V6M  [C_0603-H1_2]  208.24 55.87 90 bottom
PCV14  10U_0603_25V6M  [C_0603-H1_2]  209.46 55.87 90 bottom
PCV15  0.01U_0402_16V7K  [C_0402]  224.24 57.91 270 top
PCV16  4700P_0402_50V7K  [C_0402]  223.44 61.25 0 bottom
PCV17  0.1U_0402_25V6  [C_0402]  223.31 55.24 180 bottom
PCV18  1U_0603_25V6  [C_0603]  226.24 59.81 90 bottom
PCV19  680P_0402_50V7K  [C_0402]  196.84 60.03 270 top
PCV20  47P_0402_50V8J  [C_0402]  229.13 59.66 0 bottom
PCV21  0.1U_0402_25V6  [C_0402]  221.32 55.5 90 bottom
PCV22  0.1U_0402_25V6  [C_0402]  201.45 56.14 90 top
PCV23  2200P_0402_50V7K  [C_0402]  200.48 56.15 90 top
PCV24  10U_0603_25V6M  [C_0603-H1_2]  200.32 55.83 90 bottom
PCV25  10U_0603_25V6M  [C_0603-H1_2]  201.53 55.83 90 bottom
PCV26  1U_0201_6.3V6M  [C_0201]  221.25 60.08 270 bottom
PCV27  680P_0402_50V7K  [C_0402]  212.74 58.91 270 top
PCV28  2.2U_0402_16V6K  [C_0402]  227.82 51.41 0 bottom
PCV29  1U_0201_6.3V6M  [C_0201]  201.68 91.82 270 top
PCV30  1U_0201_6.3V6M  [C_0201]  201.68 93.74 270 top
PCV31  1U_0201_6.3V6M  [C_0201]  201.47 88.21 90 top
PCV32  1U_0201_6.3V6M  [C_0201]  206.29 81.07 0 top
PCV33  1U_0201_6.3V6M  [C_0201]  206.29 80.27 0 top
PCV34  1U_0201_6.3V6M  [C_0201]  207.77 77.62 0 top
PCV35  1U_0201_6.3V6M  [C_0201]  205.43 86.91 180 top
PCV36  1U_0201_6.3V6M  [C_0201]  201.62 86.19 270 top
PCV37  1U_0201_6.3V6M  [C_0201]  202.19 86.7 0 top
PCV38  1U_0201_6.3V6M  [C_0201]  209.36 72.97 0 bottom
PCV39  1U_0201_6.3V6M  [C_0201]  203.47 79.81 180 top
PCV40  1U_0201_6.3V6M  [C_0201]  199.24 76.59 90 top
PCV41  1U_0201_6.3V6M  [C_0201]  206.31 79.55 0 top
PCV42  4.7U_0402_6.3V6M  [C_0402]  207.48 86.9 180 top
PCV43  4.7U_0402_6.3V6M  [C_0402]  210.6 86.9 270 top
PCV44  4.7U_0402_6.3V6M  [C_0402]  208.94 85.25 90 top
PCV45  4.7U_0402_6.3V6M  [C_0402]  209.38 81.94 180 top
PCV46  4.7U_0402_6.3V6M  [C_0402]  203.74 80.79 180 top
PCV47  4.7U_0402_6.3V6M  [C_0402]  201.39 83.73 0 top
PCV48  4.7U_0402_6.3V6M  [C_0402]  202.04 77.52 270 top
PCV49  4.7U_0402_6.3V6M  [C_0402]  199.87 84.23 180 top
PCV50  4.7U_0402_6.3V6M  [C_0402]  201.93 78.53 90 top
PCV51  4.7U_0402_6.3V6M  [C_0402]  209.58 82.98 90 top
PCV52  4.7U_0402_6.3V6M  [C_0402]  208.18 82.9 90 top
PCV53  4.7U_0402_6.3V6M  [C_0402]  211.05 83.37 90 top
PCV54  4.7U_0402_6.3V6M  [C_0402]  206.17 82.19 0 top
PCV55  4.7U_0402_6.3V6M  [C_0402]  205.66 83.96 0 top
PCV56  4.7U_0402_6.3V6M  [C_0402]  205.1 85.43 0 top
PCV57  4.7U_0402_6.3V6M  [C_0402]  200.46 78.15 180 top
PCV58  330U_D1_2VM_R6M  [C_X]  199.66 65.89 270 top
PCV59  330U_D1_2VM_R6M  [C_X]  208.36 66.02 270 top
PCV60  330U_D1_2VM_R6M  [C_X]  191.02 65.6 270 bottom
PCV61  330U_D3_2.5VY_R6M  [C_X]  210.89 89.7 180 top
PCV62  4.7U_0402_6.3V6M  [C_0402]  207.16 93.45 90 top
PCV63  22U_0603_6.3V6M  [C_0603]  202.04 73.12 180 bottom
PCV64  22U_0603_6.3V6M  [C_0603]  197.72 71.93 0 bottom
PCV65  22U_0603_6.3V6M  [C_0603]  207.18 76.63 0 top
PCV66  22U_0603_6.3V6M  [C_0603]  203.43 73.12 0 bottom
PCV67  22U_0603_6.3V6M  [C_0603]  207.75 73.12 180 bottom
PCV68  22U_0603_6.3V6M  [C_0603]  197.75 76.44 90 top
PCV69  22U_0603_6.3V6M  [C_0603]  204.04 66 270 top
PCV70  22U_0603_6.3V6M  [C_0603]  209.12 70.71 0 bottom
PCV71  22U_0603_6.3V6M  [C_0603]  196.3 70.72 180 bottom
PCV72  22U_0603_6.3V6M  [C_0603]  205.1 92.9 90 top
PCV73  4.7U_0402_6.3V6M  [C_0402]  209.04 93.51 270 top
PCV74  10U_0402_6.3V6M  [C_0402]  209.56 72.14 0 bottom
PCV75  10U_0402_6.3V6M  [C_0402]  207.24 71.95 180 bottom
PCV76  10U_0402_6.3V6M  [C_0402]  207.24 70.76 180 bottom
PCV77  10U_0402_6.3V6M  [C_0402]  203.98 71.94 0 bottom
PCV78  10U_0402_6.3V6M  [C_0402]  203.98 70.74 0 bottom
PCV79  10U_0402_6.3V6M  [C_0402]  201.58 71.94 180 bottom
PCV80  10U_0402_6.3V6M  [C_0402]  201.58 70.74 180 bottom
PCV81  10U_0402_6.3V6M  [C_0402]  198.28 70.74 0 bottom
PCV82  10U_0402_6.3V6M  [C_0402]  195.86 71.79 180 bottom
PCV83  10U_0402_6.3V6M  [C_0402]  194.88 64.39 270 top
PCV84  10U_0402_6.3V6M  [C_0402]  196.02 76.49 90 top
PCV85  10U_0402_6.3V6M  [C_0402]  202.91 65.52 270 top
PCV86  10U_0402_6.3V6M  [C_0402]  202.61 90.36 270 top
PCV87  10U_0402_6.3V6M  [C_0402]  196.15 64.39 270 top
PCV88  10U_0402_6.3V6M  [C_0402]  214.98 64.65 270 top
PCV89  10U_0402_6.3V6M  [C_0402]  203.32 82.04 90 top
PCV90  10U_0402_6.3V6M  [C_0402]  203.44 93.36 270 top
PCV91  10U_0402_6.3V6M  [C_0402]  203.26 85.17 180 top
PCV92  1U_0201_6.3V6M  [C_0201]  222.39 60.06 270 bottom
PCV93  1U_0201_6.3V6M  [C_0201]  221.82 60.06 270 bottom
PCW1  0.01U_0402_16V7K  [C_0402]  241.44 56.97 180 bottom
PCW2  0.1U_0603_25V7K  [C_0603]  239.99 49.27 0 bottom
PCW3  1U_0201_6.3V6M  [C_0201]  242.51 50.49 270 bottom
PCW4  680P_0402_50V7K  [C_0402]  243.17 57.3 90 bottom
PCW5  0.1U_0402_16V7K  [C_0402]  238.7 53.1 90 bottom
PCW6  680P_0402_50V7K  [C_0402]  261.31 58.72 270 bottom
PCW7  2200P_0402_50V7K  [C_0402]  257.51 46.2 0 top
PCW8  0.1U_0402_25V6  [C_0402]  257.51 44.98 0 top
PCW9  10U_0603_25V6M  [C_0603-H1_2]  257.26 45 0 bottom
PCW10  10U_0603_25V6M  [C_0603-H1_2]  257.26 46.21 0 bottom
PCW11  390U_2.5V_ESR10M_6.3X6  [C_6P3X6]  247.9 63.98 270 bottom
PCW12  1U_0201_6.3V6M  [C_0201]  243.08 49.32 0 bottom
PCW13  1U_0201_6.3V6M  [C_0201]  243.09 49.91 0 bottom
PCW14  1U_0201_6.3V6M  [C_0201]  243.09 50.49 0 bottom
PCZ1  2200P_0402_50V7K  [C_0402]  173.64 126.52 180 bottom
PCZ2  0.01UF_0402_25V7K  [C_0402]  174.82 127.77 90 bottom
PCZ3  1U_0201_6.3V6M  [C_0201]  173.73 134.01 180 top
PCZ4  1000P_0402_50V7K  [C_0402]  175.42 125.63 180 bottom
PCZ5  1000P_0402_25V8J  [C_0402]  173.93 127.77 90 bottom
PCZ6  470P_0402_50V8J  [C_0402]  170.95 130.01 0 top
PCZ7  1000P_0402_50V7K  [C_0402]  173.64 124.86 180 top
PCZ8  3300P_0402_25V7K  [C_0402]  171.86 129.12 180 top
PCZ9  1000P_0402_50V7K  [C_0402]  170.95 128.23 0 top
PCZ10  0.015U_0402_16V7K  [C_0402]  170.95 125.69 0 top
PCZ11  100P_0402_50V8J  [C_0402]  170.95 126.58 0 top
PCZ12  1000P_0402_50V7K  [C_0402]  174.58 123.77 90 bottom
PCZ13  2200P_0402_50V7K  [C_0402]  173.69 123.01 90 bottom
PCZ14  1000P_0402_50V7K  [C_0402]  173.31 134.44 90 bottom
PCZ15  2200P_0402_50V7K  [C_0402]  171.45 134.52 0 bottom
PCZ16  47P_0402_50V8J  [C_0402]  171.39 124.8 270 top
PCZ17  470P_0402_50V8J  [C_0402]  171.98 121.36 90 bottom
PCZ18  470P_0402_50V8J  [C_0402]  169.25 126.59 270 top
PCZ19  2200P_0402_50V7K  [C_0402]  171.53 121.93 90 top
PCZ20  470P_0402_50V8J  [C_0402]  169.83 135.41 180 bottom
PCZ21  47P_0402_50V8J  [C_0402]  168.94 134.39 180 top
PCZ22  2200P_0402_50V7K  [C_0402]  168.1 136.24 270 top
PCZ23  470P_0402_50V8J  [C_0402]  171 132.56 270 top
PCZ24  100P_0402_50V8J  [C_0402]  169.31 123.16 270 top
PCZ25  820PF_0402_50V7K  [C_0402]  170.2 122.25 90 top
PCZ26  0.22U_0402_16V7K  [C_0402]  167.09 126.59 270 top
PCZ27  82P_0402_50V8J  [C_0402]  167.16 134.39 180 top
PCZ28  330P_0402_50V7K  [C_0402]  167.16 135.41 180 top
PCZ29  0.22U_0402_16V7K  [C_0402]  166.83 132.56 270 top
PCZ30  0.1U_0402_25V6  [C_0402]  162.97 125.75 180 bottom
PCZ31  0.01U_0402_25V7K  [C_0402]  162.56 126.64 0 bottom
PCZ32  0.1U_0402_25V6  [C_0402]  163.48 132.23 180 bottom
PCZ33  1U_0402_16V6K  [C_0402]  165.1 128.2 0 top
PCZ34  0.022U_0402_25V7K  [C_0402]  168.62 123.09 180 bottom
PCZ35  0.022U_0402_25V7K  [C_0402]  166.02 134.33 180 bottom
PCZ36  0.022U_0402_25V7K  [C_0402]  166.84 123.09 180 bottom
PCZ37  0.022U_0402_25V7K  [C_0402]  165.07 123.09 180 bottom
PCZ38  0.022U_0402_25V7K  [C_0402]  163.29 123.09 180 bottom
PCZ39  2.2U_0402_6.3V6M  [C_0402]  154.13 136.12 270 bottom
PCZ40  2200P_0402_50V7K  [C_0402]  156.16 130.53 270 bottom
PCZ41  0.1U_0402_25V6  [C_0402]  155.28 130.53 270 bottom
PCZ42  10U_0603_25V6M  [C_0603-H1_2]  154.64 132.8 90 bottom
PCZ43  10U_0603_25V6M  [C_0603-H1_2]  155.91 132.8 90 bottom
PCZ44  100U_25V_NC_6.3X6  [C_6P3X6]  110.69 86.51 0 bottom
PCZ45  100U_25V_NC_6.3X6  [C_6P3X6]  123.09 130.51 270 bottom
PCZ46  0.22U_0402_25V6K  [C_0402]  150.58 133.7 270 bottom
PCZ47  680P_0402_50V7K  [C_0402]  148.04 125.25 90 top
PCZ48  2200P_0402_50V7K  [C_0402]  148.67 130.53 270 bottom
PCZ49  0.1U_0402_25V6  [C_0402]  147.78 130.53 270 bottom
PCZ50  10U_0603_25V6M  [C_0603-H1_2]  147.78 132.8 90 bottom
PCZ51  10U_0603_25V6M  [C_0603-H1_2]  149.05 132.8 90 bottom
PCZ52  0.22U_0402_25V6K  [C_0402]  142.96 133.7 270 bottom
PCZ53  2.2U_0402_6.3V6M  [C_0402]  146.51 136.12 270 bottom
PCZ54  680P_0402_50V7K  [C_0402]  142.83 126.26 135 top
PCZ55  2200P_0402_50V7K  [C_0402]  141.18 130.53 270 bottom
PCZ56  0.1U_0402_25V6  [C_0402]  140.29 130.53 270 bottom
PCZ57  10U_0603_25V6M  [C_0603-H1_2]  141.31 132.8 90 bottom
PCZ58  10U_0603_25V6M  [C_0603-H1_2]  140.04 132.8 90 bottom
PCZ59  0.22U_0402_25V6K  [C_0402]  135.34 133.7 270 bottom
PCZ60  2.2U_0402_6.3V6M  [C_0402]  138.89 136.12 270 bottom
PCZ61  680P_0402_50V7K  [C_0402]  140.21 128.67 0 bottom
PCZ62  2200P_0402_50V7K  [C_0402]  133.56 130.53 270 bottom
PCZ63  0.1U_0402_25V6  [C_0402]  132.67 130.53 270 bottom
PCZ64  10U_0603_25V6M  [C_0603-H1_2]  132.54 132.8 90 bottom
PCZ65  10U_0603_25V6M  [C_0603-H1_2]  133.81 132.8 90 bottom
PCZ66  0.22U_0402_25V6K  [C_0402]  127.97 133.7 270 bottom
PCZ67  2.2U_0402_6.3V6M  [C_0402]  131.53 136.12 270 bottom
PCZ68  680P_0402_50V7K  [C_0402]  128.17 128.45 270 top
PCZ173  330U_D3_2.5VY_R6M  [C_X]  149.71 97.28 0 top
PCZ174  330U_D1_2VY_R9M  [C_X]  149.94 117.42 90 top
PCZ175  22U_0603_6.3V6M  [C_0603]  155.14 101.65 0 top
PCZ176  22U_0603_6.3V6M  [C_0603]  154.07 100.38 180 top
PCZ177  22U_0603_6.3V6M  [C_0603]  150.27 101.65 0 top
PCZ178  22U_0603_6.3V6M  [C_0603]  155.58 91.39 90 top
PCZ179  22U_0603_6.3V6M  [C_0603]  143.97 92.68 180 top
PCZ180  22U_0603_6.3V6M  [C_0603]  145.39 101.65 0 top
PCZ181  22U_0603_6.3V6M  [C_0603]  149.29 100.38 180 top
PCZ182  22U_0603_6.3V6M  [C_0603]  143.97 91.49 180 top
PCZ183  22U_0603_6.3V6M  [C_0603]  152.63 91.36 90 top
PCZ184  22U_0603_6.3V6M  [C_0603]  144.44 100.38 180 top
PCZ185  22U_0603_6.3V6M  [C_0603]  144.44 101.65 180 top
PCZ186  22U_0603_6.3V6M  [C_0603]  155.14 100.38 0 top
PCZ187  22U_0603_6.3V6M  [C_0603]  154.07 101.65 180 top
PCZ188  22U_0603_6.3V6M  [C_0603]  150.27 100.38 0 top
PCZ189  22U_0603_6.3V6M  [C_0603]  145.42 91.49 0 top
PCZ190  22U_0603_6.3V6M  [C_0603]  145.39 100.38 0 top
PCZ191  22U_0603_6.3V6M  [C_0603]  149.29 101.65 180 top
PCZ192  22U_0603_6.3V6M  [C_0603]  159.77 91.49 180 top
PCZ193  22U_0603_6.3V6M  [C_0603]  156.8 91.39 90 top
PCZ217  1U_0201_6.3V6M  [C_0201]  149.31 103.69 180 top
PCZ218  1U_0201_6.3V6M  [C_0201]  144.45 103.12 180 top
PCZ219  1U_0201_6.3V6M  [C_0201]  147.5 103.69 0 top
PCZ220  1U_0201_6.3V6M  [C_0201]  151.72 103.13 180 top
PCZ221  1U_0201_6.3V6M  [C_0201]  149.94 103.12 0 top
PCZ222  1U_0201_6.3V6M  [C_0201]  151.72 103.71 180 top
PCZ223  1U_0201_6.3V6M  [C_0201]  149.31 103.12 180 top
PCZ224  1U_0201_6.3V6M  [C_0201]  147.5 103.12 0 top
PCZ225  1U_0201_6.3V6M  [C_0201]  146.89 103.69 180 top
PCZ226  1U_0201_6.3V6M  [C_0201]  145.09 103.69 0 top
PCZ227  1U_0201_6.3V6M  [C_0201]  156.52 103.66 180 top
PCZ228  1U_0201_6.3V6M  [C_0201]  154.73 103.08 0 top
PCZ229  1U_0201_6.3V6M  [C_0201]  154.11 103.72 180 top
PCZ230  1U_0201_6.3V6M  [C_0201]  157.14 103.08 0 top
PCZ231  1U_0201_6.3V6M  [C_0201]  146.89 103.12 180 top
PCZ232  1U_0201_6.3V6M  [C_0201]  145.09 103.12 0 top
PCZ233  1U_0201_6.3V6M  [C_0201]  156.52 103.08 180 top
PCZ234  1U_0201_6.3V6M  [C_0201]  154.73 103.66 0 top
PCZ235  1U_0201_6.3V6M  [C_0201]  154.11 103.15 180 top
PCZ236  1U_0201_6.3V6M  [C_0201]  157.14 103.66 0 top
PCZ237  1U_0201_6.3V6M  [C_0201]  144.45 103.69 180 top
PCZ238  1U_0201_6.3V6M  [C_0201]  152.33 103.71 0 top
PCZ239  1U_0201_6.3V6M  [C_0201]  149.94 103.69 0 top
PCZ240  1U_0201_6.3V6M  [C_0201]  152.33 103.13 0 top
PCZ307  22U_0603_6.3V6M  [C_0603]  144.48 96.04 180 top
PCZ308  22U_0603_6.3V6M  [C_0603]  144.56 99.11 180 top
PCZ309  22U_0603_6.3V6M  [C_0603]  145.72 99.11 0 top
PCZ310  22U_0603_6.3V6M  [C_0603]  144 97.61 180 top
PCZ311  22U_0603_6.3V6M  [C_0603]  151.41 91.36 90 top
PCZ312  22U_0603_6.3V6M  [C_0603]  145.39 92.71 0 top
PCZ313  22U_0603_6.3V6M  [C_0603]  145.47 96.04 0 top
PCZ314  22U_0603_6.3V6M  [C_0603]  153.85 91.36 90 top
PCZ315  22U_0603_6.3V6M  [C_0603]  159.77 92.68 180 top
PD1  CEST23NC24VU_SOT23-3  [L30ESD24VC3-2_SOT23-3]  281.89 40.82 180 top
PD2  CEST23NC24VU_SOT23-3  [L30ESD24VC3-2_SOT23-3]  283.93 27.54 90 bottom
PD3  LUDZS3.6BT1G_SOD323-2  [LUDZS3P6BT1G_SOD323-2]  285.73 38.76 0 top
PDB01  -  [BAS40CW_SOT323-3]  236.19 9.3 0 bottom
PDB02  -  [BAS40CW_SOT323-3]  229.89 12.56 180 bottom
PDB03  30MA_30V_0.5UA_0.4V_SOD323-2  [D_SOD323-2]  245.41 11.8 270 top
PDM1  CSB3D751M-40 SOD-323  [RB751V-40_SOD323-2]  94.47 20.94 180 bottom
PDM2  CSB3D751M-40 SOD-323  [RB751V-40_SOD323-2]  88.96 20.93 0 bottom
PDM3  30MA_30V_0.5UA_0.4V_SOD323-2  [D_SOD323-2]  87.16 27.72 180 bottom
PDP1  -  [SX34_SMA2]  87.33 34.57 90 bottom
PH1  100K_0402_1%_B25/50 4250K  [R_0402]  134.24 97.31 0 top
PH2  100K_0402_1%_B25/50 4250K  [R_0402]  263.05 36.09 180 top
PHZ1  220K_0402_5%_B25/50 4700K  [R_0402]  117.71 103.83 90 bottom
PHZ2  100K_0402_1%_B25/50 4250K  [R_0402]  162.39 118.97 270 bottom
PHZ3  220K_0402_5%_B25/50 4700K  [R_0402]  156.42 116.05 270 bottom
PHZ4  220K_0402_5%_B25/50 4700K  [R_0402]  156.11 131.85 180 bottom
PHZ5  220K_0402_5%_B25/50 4700K  [R_0402]  115.14 96.67 270 bottom
PJ301  -  [JUMP_43X79]  244.72 31.25 0 bottom
PJ302  -  [JUMP_43X118]  245.86 19.04 90 top
PJ303  -  [JUMP_43X39]  250.82 26.71 270 bottom
PJ304  -  [JUMP_43X79]  82.13 7.53 270 top
PJ305  -  [JUMP_43X118]  68.29 15.39 0 bottom
PJ306  -  [JUMP_43X39]  79.52 11.73 90 bottom
PJ1001  -  [JUMP_43X79]  239.81 31.8 270 bottom
PJ1002  -  [JUMP_43X118]  229.79 21.06 180 top
PJ1801  -  [JUMP_43X79]  270.08 19.85 180 bottom
PJ1802  -  [JUMP_43X79]  260.27 24.96 90 bottom
PJ2501  JUMP_43X39  [JUMP_43X39_0805]  104.42 20.08 0 top
PJ2502  JUMP_43X39  [JUMP_43X39_0805]  113.05 20.36 180 top
PJB1  -  [JUMP_43X118]  251.36 14.46 270 top
PJF1  -  [JUMP_43X79]  172.04 103.02 315 bottom
PJF2  -  [JUMP_43X79]  181.12 95.98 315 bottom
PJH1  -  [JUMP_43X79]  186.19 97.02 90 bottom
PJH2  -  [JUMP_43X118]  175.09 108.35 225 bottom
PJM1  -  [JUMP_43X79]  91.37 41.75 270 top
PJM2  -  [JUMP_43X118]  96.28 38.26 0 top
PJM3  JUMP_43X39  [JUMP_43X39_0805]  95.46 30.3 0 bottom
PJP1  ACES_59012-0120N-005  [ACES_59012-0120N-005_12P-T]  290.95 33.35 0 bottom
PJPB1  ACES_50279-01201-001  [ACES_50279-01201-001_12P-T]  288.25 7.9 90 bottom
PJPP2  -  [JUMP_43X39]  83.34 43.2 180 top
PJV1  -  [JUMP_43X118]  227.77 44.34 90 top
PJW1  -  [JUMP_43X118]  246.99 63.34 45 top
PJW2  -  [JUMP_43X118]  250.74 59.58 45 top
PJW5  -  [JUMP_43X79]  251.22 44.65 270 bottom
PJZ1  -  [JUMP_43X118]  104.73 75.76 270 top
PL11  5A Z80 20M 0805  [TAI-T_HCB2012KF-121T50_2P]  277.85 32.4 180 top
PL12  5A Z80 20M 0805  [TAI-T_HCB2012KF-121T50_2P]  277.85 34.69 180 top
PL13  5A Z80 20M 0805  [TAI-T_HCB2012KF-121T50_2P]  274 6.66 180 bottom
PL14  5A Z80 20M 0805  [TAI-T_HCB2012KF-121T50_2P]  274 8.56 180 bottom
PL301  1.5UH_9A_20%_7X7X3_M  [L_7X7X3_M]  245.82 25.57 270 bottom
PL302  1.5UH_9A_20%_7X7X3_M  [L_7X7X3_M]  71.89 8.99 180 bottom
PL1001  1UH_11A_20%_7X7X3_M  [L_7X7X3_M_2P]  230.26 24.95 270 bottom
PL1801  1UH_MHCD252012A-1R0M-A8S_3A_20%  [CHILI_MHCD252012A-1R0M-A8S_2P]  261.56 19.56 180 bottom
PL2501  1UH_MHCD252012A-1R0M-A8S_3A_20%  [CHILI_MHCD252012A-1R0M-A8S_2P]  110.98 17.9 0 top
PLA1  0.47UH_NA__12.2A_20%  [L_5X5X3_M]  158.96 121.58 270 bottom
PLB02  4.7UH_5.5A _20%_7X7X3_M  [L_7X7X3_M_2P]  256.53 9.19 0 bottom
PLF1  1UH_MHCD252012A-1R0M-A8S_3A_20%  [CHILI_MHCD252012A-1R0M-A8S_2P]  177.63 97.9 315 bottom
PLG1  0.15UH_MMD06BZER15MEM_22A_20%  [MAG_MMD06BZER15MEM_4P]  110.19 100.86 0 bottom
PLH1  1UH_6.6A_20%_5X5X3_M  [L_5X5X3_M_2P]  184.15 108.99 135 bottom
PLM1  1UH_11A_20%_7X7X3_M  [L_7X7X3_M_2P]  92.66 40.13 270 bottom
PLP1  2.2UH_TMPC0412HP-2R2MG-Z03_3.3A_20%  [TAI-T_TMPC0412HP-2R2MG-Z03_2P]  81.04 39.01 0 top
PLV1  0.24UH_22A_+-20%_ 7X7X3_M  [L_7X7X3_M]  204.87 62.16 90 bottom
PLV2  0.24UH_22A_+-20%_ 7X7X3_M  [L_7X7X3_M]  197.17 62.16 90 bottom
PLV3  0.24UH_22A_+-20%_ 7X7X3_M  [L_7X7X3_M]  212.61 62.16 90 bottom
PLW1  0.82UH_PCMC063T-R82MN_13A_20%  [CYNTE_PCMC063T-R82MN_2P]  254.9 56.22 90 bottom
PLZ1  0.15UH_NA__35A_20%  [L_7X7X3_M]  152.1 123.32 270 bottom
PLZ2  0.15UH_NA__35A_20%  [L_7X7X3_M]  144.48 123.32 270 bottom
PLZ3  0.15UH_NA__35A_20%  [L_7X7X3_M]  136.86 123.32 270 bottom
PLZ4  0.15UH_NA__35A_20%  [L_7X7X3_M]  129.24 123.32 270 bottom
PQ1  -  [2N7002KW_SOT323-3]  275.53 11.9 0 top
PQ2  -  [2N7002KDW_SOT363-6]  273.09 16.42 270 top
PQA1  -  [AONH36334_DFN3X3A8-10]  156.73 124.4 90 bottom
PQB01  AONS32304_1N_DFN56-8-5  [Q_N_DFN56-8-5]  267.76 34.85 270 top
PQB02  -  [2N7002KW_SOT323-3]  262.43 37.71 270 top
PQB03  -  [AON7380_DFN3X3-8-5]  265.71 32.83 90 top
PQB04  -  [AON7380_DFN3X3-8-5]  265.48 9.22 90 bottom
PQB05  -  [AONH36334_DFN3X3A8-10]  253.35 11.18 180 top
PQG1  -  [AOE6930_DFN5X6E8-10]  113.87 90.83 180 bottom
PQM1  -  [AONH36334_DFN3X3A8-10]  93.51 33.19 90 top
PQV1  -  [AOE6930_DFN5X6E8-10]  206.75 54.04 180 bottom
PQV2  -  [AOE6930_DFN5X6E8-10]  198.78 54 180 bottom
PQV3  -  [AOE6930_DFN5X6E8-10]  214.68 54.04 180 bottom
PQW1  -  [AON6380_DFN5X6-8-5]  252.68 53.4 0 bottom
PQW2  AON6314_N_DFN56-8-5  [Q_N_DFN56-8-5]  262.54 47.86 180 bottom
PQW3  LBSS139WT1G_SC70-3  [2N7002KW_SOT323-3]  237.03 55.16 0 bottom
PQZ1  -  [AOE6930_DFN5X6E8-10]  150.2 131.42 0 bottom
PQZ2  -  [AOE6930_DFN5X6E8-10]  142.58 131.42 0 bottom
PQZ3  -  [AOE6930_DFN5X6E8-10]  134.96 131.42 0 bottom
PQZ4  -  [AOE6930_DFN5X6E8-10]  127.59 131.42 0 bottom
PR1  0_0402_5%  [R0402_0OHM]  281.34 27.9 0 bottom
PR2  100K_0402_5%  [R_0402]  281.44 27.09 180 bottom
PR3  10K_0402_1%  [R_0402]  284.43 38.3 90 top
PR4  243_0402_1%  [R_0402]  281.34 28.8 0 bottom
PR5  10K_0402_1%  [R_0402]  286.21 40.08 90 top
PR6  100K_0402_5%  [R_0402]  280.55 28.79 270 bottom
PR9  16.2K_0402_1%  [R_0402]  132.34 17.93 0 top
PR10  16.2K_0402_1%  [R_0402]  131.07 24.47 0 top
PR14  100_0402_5%  [R_0402]  284.18 11.83 180 top
PR15  100_0402_5%  [R_0402]  284.18 12.72 180 top
PR16  100K_0402_5%  [R_0402]  284.18 15.43 180 top
PR17  100_0402_5%  [R_0402]  284.18 14.63 180 top
PR18  470K_0402_5%  [R_0402]  273.44 18.44 0 top
PR19  3.6K_0402_1%  [R_0402]  269.99 15.39 0 top
PR20  1M_0402_5%  [R_0402]  274.35 17.55 180 top
PR21  0_0402_5%  [R0402_0OHM]  284.18 13.49 180 top
PR22  3.6K_0402_1%  [R_0402]  275.05 9.26 90 top
PR301  0_0402_5%  [R0402_0OHM]  246.62 27.94 180 bottom
PR302  4.7_1206_5%  [R_1206]  250.65 24.41 270 bottom
PR303  100K_0402_5%  [R_0402]  253.55 34.2 180 bottom
PR304  1K_0402_1%  [R_0402]  253.63 28.99 180 bottom
PR305  0_0402_5%  [R0402_0OHM]  77.47 6.67 180 top
PR306  499K_0402_1%  [R_0402]  76.04 13.73 180 bottom
PR307  4.7_1206_5%  [R_1206]  72.64 6.49 180 top
PR308  150K_0402_1%  [R_0402]  74.98 12.58 0 bottom
PR309  0_0402_5%  [R_0402]  74.21 11.87 90 bottom
PR310  2.2K_0402_5%  [R_0402]  255.53 29.79 180 bottom
PR311  0_0402_5%  [R0402_0OHM]  255.53 30.55 180 bottom
PR312  1K_0402_1%  [R_0402]  77.82 12.73 270 bottom
PR313  1M_0402_1%  [R_0402]  253.42 30.66 90 bottom
PR314  0_0402_5%  [R_0402]  252.65 32.54 90 bottom
PR1002  0_0402_5%  [R_0402]  240.34 22.79 270 bottom
PR1003  0_0402_5%  [R0402_0OHM]  241.71 23.56 180 bottom
PR1004  0_0402_5%  [R_0402]  241.18 21.87 90 bottom
PR1005  1M_0402_1%  [R_0402]  240.77 24.86 0 bottom
PR1006  100K_0402_1%  [R_0402]  237.93 22.95 90 bottom
PR1007  133K_0402_1%  [R_0402]  239.55 23.83 270 bottom
PR1009  0_0402_5%  [R0402_0OHM]  236.47 30.12 180 bottom
PR1013  4.7_1206_5%  [R_1206]  232.34 28.39 270 top
PR1020  1K_0402_1%  [R_0402]  238.72 22.95 90 bottom
PR1801  100K_0402_5%  [R_0402]  266.95 23.4 270 bottom
PR1802  4.7_0603_5%  [R_0603]  262.76 18.7 0 bottom
PR1803  20.5K_0402_1%  [R_0402]  265.19 23.35 0 bottom
PR1804  0_0402_5%  [R0402_0OHM]  264.37 23.39 180 bottom
PR1805  1M_0402_5%  [R_0402]  262.68 22.49 180 bottom
PR1806  10K_0402_1%  [R_0402]  266.56 21.36 0 bottom
PR2501  0_0402_5%  [R_0402]  107.02 13.6 90 top
PR2502  0_0402_5%  [R_0402]  107.84 13.59 90 top
PR2503  1M_0402_1%  [R_0402]  108.64 14.51 270 top
PR2504  100K_0402_5%  [R_0402]  104.25 16.57 0 top
PR2505  4.7_0402_5%  [R_0402]  111.37 19.66 180 top
PR2506  32.4K_0402_1%  [R_0402]  106.02 13.96 90 top
PR2507  10K_0402_1%  [R_0402]  105.16 15.77 180 top
PRA1  2.2_0603_5%  [R_0603]  158.07 134.2 270 bottom
PRA2  0_0603_5%  [R_0603]  159.59 129.75 90 top
PRA3  4.7_1206_5%  [R_1206]  157.97 121.43 90 top
PRB01  1M_0402_1%  [R_0402]  266.17 38.02 270 top
PRB02  3M_0402_5%  [R_0402]  265.4 37.11 90 top
PRB03  0.005_1206_1%  [R_1206_4P-D]  261.42 34.54 180 top
PRB04  4.12K_0603_1%  [R_0603]  266.1 30.9 180 top
PRB06  100_0402_1%  [R_0402]  240.65 14 90 top
PRB07  4.12K_0603_1%  [R_0603]  266.1 29.63 180 top
PRB08  0.005_1206_1%  [R_1206_4P-D]  266.55 6.87 0 bottom
PRB10  422K_0402_1%  [R_0402]  234.54 10.53 0 bottom
PRB11  10_1206_5%  [R_1206]  240.74 8.35 180 bottom
PRB12  64.9K_0402_1%  [R_0402]  235.67 11.41 0 bottom
PRB13  2.2_0603_5%  [R_0603]  241.99 13.82 0 top
PRB14  0_0603_5%  [R_0603]  241.79 12.58 0 top
PRB15  0_0402_5%  [R0402_0OHM]  233.63 11.46 0 top
